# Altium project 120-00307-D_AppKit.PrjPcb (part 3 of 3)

## Sheet 13-JLINK_2.SchDoc: APP KIT BOARD
size 431 x 279 mm; Organization: ORGANIZATION; Address1: ADDRESS 1; Address2: ADDRESS 2; Address3: ADDRESS 3; Address4: ADDRESS 4; DocumentNumber: 13; Revision: -; SheetNumber: 13; SheetTotal: 14; ENG_APP_DATE: --/--/--; DSN_APP_DATE: --/--/--; CHK_APP_DATE: --/--/--
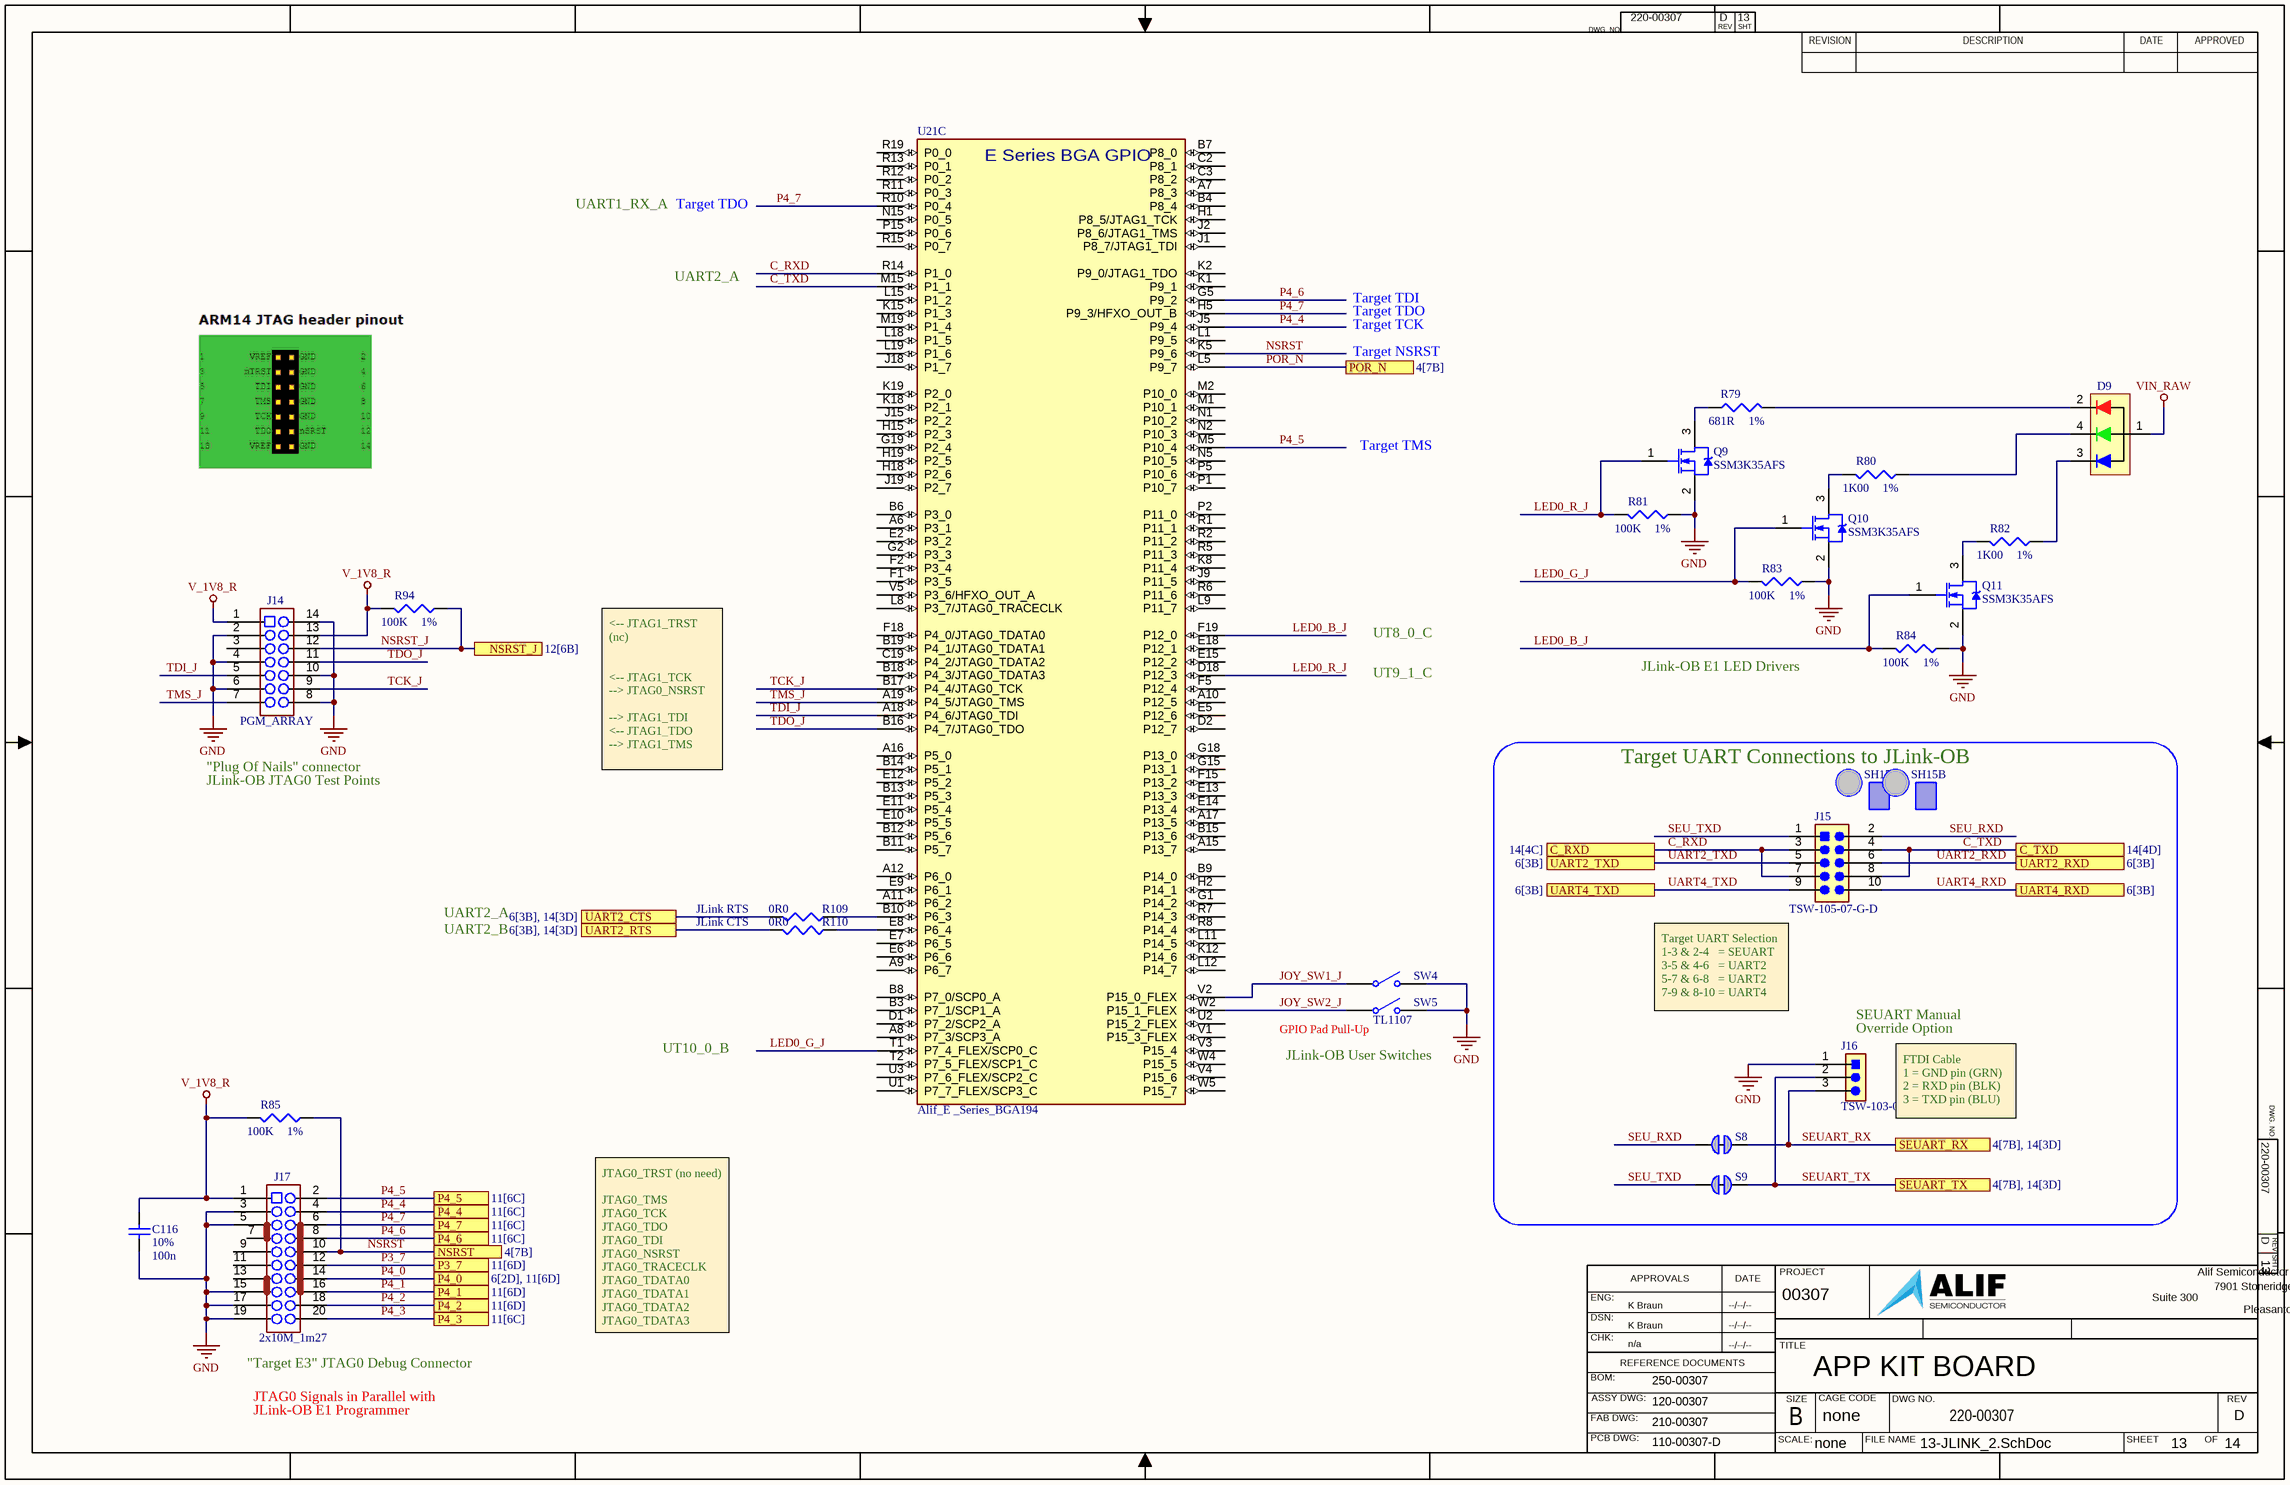
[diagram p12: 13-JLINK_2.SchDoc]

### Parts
C116  value 100n  Tolerance: 10%  [CAPC0402-01]  (hidden comment: Cap)
D9  SML-LX0404SIUPGUSB  [LED_SML-LX0404_LUM]  (value not drawn)
J14  value PGM_ARRAY  [TC2070-IDC]  (hidden comment: PGMG_CONTACT,14P,TC2070-IDC_1)  (no BOM)
J15  TSW-105-07-G-D  [CONN_TSW-105-07-G-D_SAI]
J16  TSW-103-07-G-S  [CONN_HDR_1X3_STRT_0.100]
J17  value 2x10M_1m27  [SAMTEC_FTSH-110-01-X-DV-007-K]  (hidden comment: Hdr_M_2X10_1M27_STRT_KEY_CORTEX_1)
Q9  Manufacturer Part Number 1: SSM3K35AFS  [SC75_SSM_TOS-L]  (hidden comment: NMOS-2_SOT)
Q10  Manufacturer Part Number 1: SSM3K35AFS  [SC75_SSM_TOS-L]  (hidden comment: NMOS-2_SOT)
Q11  Manufacturer Part Number 1: SSM3K35AFS  [SC75_SSM_TOS-L]  (hidden comment: NMOS-2_SOT)
R79  value 681R  Tolerance: 1%  [RESC0402-01]  (hidden comment: Res3)
R80  value 1K00  Tolerance: 1%  [RESC0402-01]  (hidden comment: Res3)
R81  value 100K  Tolerance: 1%  [RESC0402-01]  (hidden comment: Res3)
R82  value 1K00  Tolerance: 1%  [RESC0402-01]  (hidden comment: Res3)
R83  value 100K  Tolerance: 1%  [RESC0402-01]  (hidden comment: Res3)
R84  value 100K  Tolerance: 1%  [RESC0402-01]  (hidden comment: Res3)
R85  value 100K  Tolerance: 1%  [RESC0402-01]  (hidden comment: Res3)
R94  value 100K  Tolerance: 1%  [RESC0402-01]  (hidden comment: Res3)
R109  value 0R0  [RESC0402-01]  (hidden comment: Res3)
R110  value 0R0  [RESC0402-01]  (hidden comment: Res3)
S8  SolderJumperShorted_Small  [Solderbridge_Shorted]  (value not drawn)  (net tie, no BOM)
S9  SolderJumperShorted_Small  [Solderbridge_Shorted]  (value not drawn)  (net tie, no BOM)
SH15A  Shunt  (value not drawn)  (mechanical)
SH15B  Shunt  (value not drawn)  (mechanical)
SW4  SW-SPST  [SW_1825966-TL1107-1]  (value not drawn)
SW5  value TL1107  [SW_1825966-TL1107-1]  (hidden comment: SW-SPST)
U21  Alif_E _Series_BGA194  [BGA194 _CENTERED]  (part C of 4)

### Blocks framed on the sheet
Target UART Connections to JLink-OB: J15 J16 S8 S9 SH15A SH15B

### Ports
C_RXD (see 14[4C]), C_TXD (see 14[4D]), NSRST (see 4[7B]), NSRST_J (see 12[6B]), P3_7 (see 11[6D]), P4_0 (see 6[2D], 11[6D]), P4_1 (see 11[6D]), P4_2 (see 11[6D]), P4_3 (see 11[6C]), P4_4 (see 11[6C]), P4_5 (see 11[6C]), P4_6 (see 11[6C]), P4_7 (see 11[6C]), POR_N (see 4[7B]), SEUART_RX (see 4[7B], 14[3D]), SEUART_TX (see 4[7B], 14[3D]), UART2_CTS (see 6[3B], 14[3D]), UART2_RTS (see 6[3B], 14[3D]), UART2_RXD (see 6[3B]), UART2_TXD (see 6[3B]), UART4_RXD (see 6[3B]), UART4_TXD (see 6[3B])

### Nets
GND: C116.2 J14.2 J14.4 J14.6 J14.8 J14.10 J14.14 J16.1 J17.3 J17.5 J17.15 J17.17 J17.19 Q9.2(S) Q10.2(S) Q11.2(S) R81.1 R83.1 R84.1 SW4.2(NO) SW5.2(NO)
V_1V8_R: C116.1 J14.1 J14.13 J17.1 R85.2 R94.2
VIN_RAW: D9.1(A)
C_RXD: J15.3 J15.7 U21.R14(P1_0) ; port C_RXD
C_TXD: J15.4 J15.8 U21.M15(P1_1) ; port C_TXD
JOY_SW1_J: SW4.1(COMMON) U21.V2(P15_0_FLEX)
JOY_SW2_J: SW5.1(COMMON) U21.W2(P15_1_FLEX)
LED0_B_J: Q11.1(G) R84.2 U21.F19(P12_0)
LED0_G_J: Q10.1(G) R83.2 U21.T1(P7_4_FLEX/SCP0_C)
LED0_R_J: Q9.1(G) R81.2 U21.D18(P12_3)
NSRST: J17.10 R85.1 U21.K5(P9_6) ; port NSRST
NSRST_J: J14.12 R94.1 ; port NSRST_J
P3_7: J17.12 ; port P3_7
P4_0: J17.14 ; port P4_0
P4_1: J17.16 ; port P4_1
P4_2: J17.18 ; port P4_2
P4_3: J17.20 ; port P4_3
P4_4: J17.4 U21.J5(P9_4) ; port P4_4
P4_5: J17.2 U21.M5(P10_4) ; port P4_5
P4_6: J17.8 U21.G5(P9_2) ; port P4_6
P4_7: J17.6 U21.H5(P9_3/HFXO_OUT_B) U21.R10(P0_4) ; port P4_7
P6_3: R109.2 ; port UART2_CTS
P6_4: R110.2 ; port UART2_RTS
POR_N: U21.L5(P9_7) ; port POR_N
SEU_RXD: J15.2 S8.1
SEU_TXD: J15.1 S9.1
SEUART_RX: J16.3 S8.2 ; port SEUART_RX
SEUART_TX: J16.2 S9.2 ; port SEUART_TX
TCK_J: J14.9 U21.B17(P4_4/JTAG0_TCK)
TDI_J: J14.5 U21.A18(P4_6/JTAG0_TDI)
TDO_J: J14.11 U21.B16(P4_7/JTAG0_TDO)
TMS_J: J14.7 U21.A19(P4_5/JTAG0_TMS)
UART2_RXD: J15.6 ; port UART2_RXD  [project net P1_0]
UART2_TXD: J15.5 ; port UART2_TXD  [project net P1_1]
UART4_RXD: J15.10 ; port UART4_RXD  [project net P12_1]
UART4_TXD: J15.9 ; port UART4_TXD  [project net P12_2]
NetD9_2: D9.2(RK) R79.2
NetD9_3: D9.3(BK) R82.1
NetD9_4: D9.4(GK) R80.1
NetQ9_3: Q9.3(D) R79.1
NetQ10_3: Q10.3(D) R80.2
NetQ11_3: Q11.3(D) R82.2
NetR109_1: R109.1 U21.B10(P6_3)
NetR110_1: R110.1 U21.E8(P6_4)

Not connected (* = marked no-connect by the designer): J14 3; J17 7 9 11 13; U21 A6(P3_1) A7(P8_3) A8(P7_3/SCP3_A) A9(P6_7) A10(P12_5) A11(P6_2) A12(P6_0) A15(P13_7) A16(P5_0) A17(P13_5) B3(P7_1/SCP1_A) B4(P8_4) B6(P3_0) B7(P8_0) B8(P7_0/SCP0_A) B9(P14_0) B11(P5_7) B12(P5_6) B13(P5_3) B14(P5_1) B15(P13_6) B18(P4_3/JTAG0_TDATA3) B19(P4_1/JTAG0_TDATA1) C2(P8_1) C3(P8_2) C19(P4_2/JTAG0_TDATA2) D1(P7_2/SCP2_A) D2(P12_7) E2(P3_2) E5(P12_6) E6(P6_6) E7(P6_5) E9(P6_1) E10(P5_5) E11(P5_4) E12(P5_2) E13(P13_3) E14(P13_4) E15(P12_2) E18(P12_1) F1(P3_5) F2(P3_4) F5(P12_4) F15(P13_2) F18(P4_0/JTAG0_TDATA0) G1(P14_2) G2(P3_3) G15(P13_1) G18(P13_0) G19(P2_4) H1(P8_5/JTAG1_TCK) H2(P14_1) H15(P2_3) H18(P2_6) H19(P2_5) J1(P8_7/JTAG1_TDI) J2(P8_6/JTAG1_TMS) J9(P11_5) J15(P2_2) J18(P1_7) J19(P2_7) K1(P9_1) K2(P9_0/JTAG1_TDO) K8(P11_4) K12(P14_6) K15(P1_3) K18(P2_1) K19(P2_0) L1(P9_5) L8(P3_7/JTAG0_TRACECLK) L9(P11_7) L11(P14_5) L12(P14_7) L15(P1_2) L18(P1_5) L19(P1_6) M1(P10_1) M2(P10_0) M19(P1_4) N1(P10_2) N2(P10_3) N5(P10_5) N15(P0_5) P1(P10_7) P2(P11_0) P5(P10_6) P15(P0_6) R1(P11_1) R2(P11_2) R5(P11_3) R6(P11_6) R7(P14_3) R8(P14_4) R11(P0_3) R12(P0_2) R13(P0_1) R15(P0_7) R19(P0_0) T2(P7_5_FLEX/SCP1_C) U1(P7_7_FLEX/SCP3_C) U2(P15_2_FLEX) U3(P7_6_FLEX/SCP2_C) V1(P15_3_FLEX) V3(P15_4) V4(P15_6) V5(P3_6/HFXO_OUT_A) W4(P15_5) W5(P15_7)

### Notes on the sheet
- UART1_RX_A
- Target TDO
- UART2_A
- Target TDI
- Target TCK
- Target NSRST
- Target TMS
- UT8_0_C
- UT9_1_C
- JLink-OB E1 LED Drivers
- <-- JTAG1_TRST (nc)
  <-- JTAG1_TCK
  --> JTAG0_NSRST
  --> JTAG1_TDI
  <-- JTAG1_TDO
  --> JTAG1_TMS
- JLink-OB JTAG0 Test Points
- "Plug Of Nails" connector
- UART2_B
- JLink RTS
- JLink CTS
- (near SW5) GPIO Pad Pull-Up
- (near J15) Target UART Selection
  1-3 & 2-4   = SEUART
  3-5 & 4-6   = UART2
  5-7 & 6-8   = UART2
  7-9 & 8-10 = UART4
- (near J16) SEUART Manual
- (near J16) Override Option
- UT10_0_B
- (near SW5) JLink-OB User Switches
- FTDI Cable
  1 = GND pin (GRN)
  2 = RXD pin (BLK)
  3 = TXD pin (BLU)
- (near J17) "Target E3" JTAG0 Debug Connector
- JTAG0_TRST (no need)
  JTAG0_TMS
  JTAG0_TCK
  JTAG0_TDO
  JTAG0_TDI
  JTAG0_NSRST
  JTAG0_TRACECLK
  JTAG0_TDATA0
  JTAG0_TDATA1
  JTAG0_TDATA2
  JTAG0_TDATA3
- JTAG0 Signals in Parallel with
- JLink-OB E1 Programmer

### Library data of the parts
C116 = Cap: Cap,100nF,10%,50V,X7R,0402; Manufacturer 1: TDK; Manufacturer Part Number 1: C1005X7R1H104K050BE; PCB_Footprint: CC0402
D9 = D LED_RGB_CA_1MMc1MM: Diode,LED,RGB, (@2mA) -> R=10mcd & 1.75V, G = 50mcd & 2.75V, B = 20mcd & 2.95V, 0404(1mm x 1mm); Manufacturer 1: Lumex
J14 = PGMG_CONTACT,14P,TC2070-IDC_1: Test Point, Array, Alignment Pins, SMT Pad,--not a BOM item--
J15 = Hdr_M_2X5_2M54_STRT_UNSHROUDED: Hdr, Male,2x5, 2.54mm, 0.230mate,0.100-0.120post,Strt; Manufacturer 1: Samtec; Manufacturer Part Number 1: TSW-105-07-L-D
J16 = Hdr_M_1X3_2M54_STRT_UNSHROUD: Hdr, 0.025" SQ Post Header, Through-hole, Vertical, -55 to 125 degC, 2.54 mm Pitch, 3-Pin, Male, RoHS; Manufacturer: Samtec; Manufacturer Part Number 1: TSW-103-07-L-S; Pitch: 2.54 mm
J17 = Hdr_M_2X10_1M27_STRT_KEY_CORTEX_1: Hdr,Male,2x10,1.27mm,Strt,Keyed,Cortex-JTAG; Manufacturer 1: Samtec; Manufacturer Part Number 1: FTSH-110-01-L-DV-007-K; PCB_Footprint: FTSH-110-01-X-DV-007-K
Q9-Q11 = NMOS-2_SOT: MOSFET,N-CH,20V,250mA,1.1Ohm,SOT-23; Manufacturer 1: Toshiba; Note: Pin 2 is electrically connected to pin 4.; Value: 20V  180mA  2.4Ohm
R79 = Res3: Res,681R,1%,100ppm,0402; Manufacturer 1: Stackpol; Manufacturer Part Number 1: RMCF0402FT681R; Wattage: 63mW
R80 R82 = Res3: Res,1K00,1%,100ppm,0402; Manufacturer 1: Stackpol; Manufacturer Part Number 1: RMCF0402FT1K; Wattage: 63mW
R81 R83-R85 R94 = Res3: Res,100K,1%,100ppm,0402; Manufacturer 1: Stackpol; Manufacturer Part Number 1: RMCF0402FT100K; Wattage: 63mW
R109 R110 = Res3: Res,0R ohm,Jumper,0402; Manufacturer 1: Stackpol; Manufacturer Part Number 1: RMCF0402ZT0R00; Wattage: 63mW; Tolerance: JMPR
S8 S9 = SolderJumperShorted_Small: DNI,Solderable Jumper,Shorted; Wattage: 63mW; PCB_Footprint: SSHORTED
SH15A SH15B = SHUNT_F_1x2_2.5MM_STRT: Shunt,Female,1x2,2.54mm,Gold,Strt; Manufacturer 1: Samtec; Manufacturer Part Number 1: SNT-100-BK-H
SW4 = SW-SPST: Swit, SPST, Momentary Pushputton, 2 pin, 6.0x3.5mm, H=5.0mm; Manufacturer 1: E-Switch; Manufacturer Part Number 1: TL1107BF180WQ; Value: TL1107
SW5 = SW-SPST: Swit, SPST, Momentary Pushputton, 2 pin, 6.0x3.5mm, H=5.0mm; Manufacturer 1: E-Switch; Manufacturer Part Number 1: TL1107BF180WQ
U21 = E7_B0_194BGA: IC,Alif E7 MCU, Rev B silicon,BGA194; Manufacturer 1: Alif Semi; Manufacturer Part Number 1: AE101F4071542LH

## Sheet 14-CypressSEUART.SchDoc: APP KIT BOARD
size 431 x 279 mm; Organization: ORGANIZATION; Address1: ADDRESS 1; Address2: ADDRESS 2; Address3: ADDRESS 3; Address4: ADDRESS 4; DocumentNumber: 14; Revision: -; SheetNumber: 14; SheetTotal: 14; ENG_APP_DATE: --/--/--; DSN_APP_DATE: --/--/--; CHK_APP_DATE: --/--/--
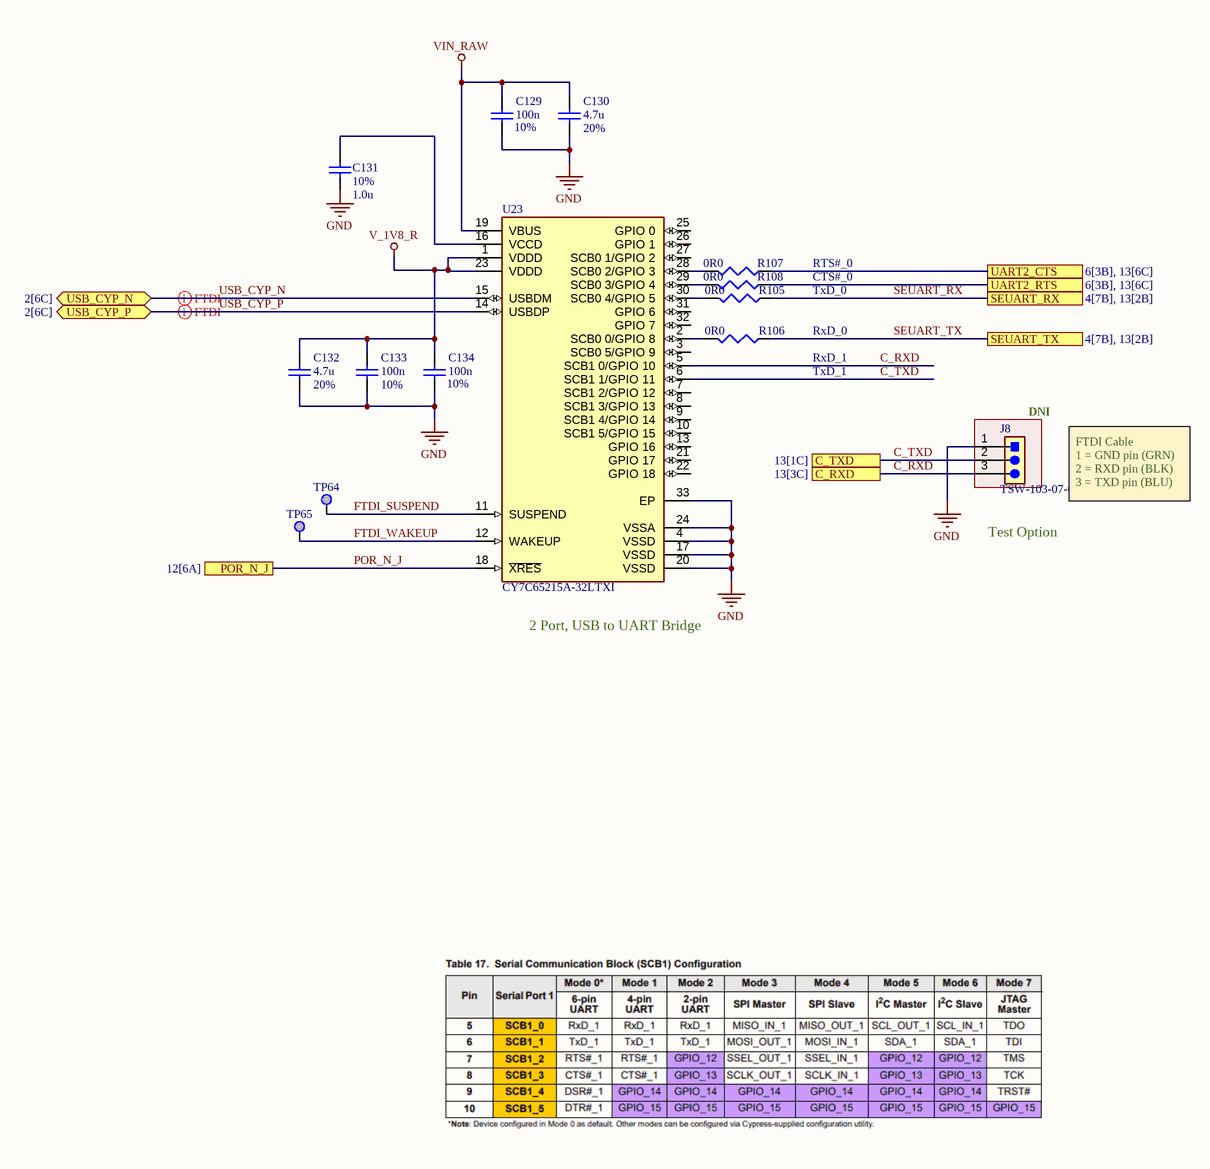
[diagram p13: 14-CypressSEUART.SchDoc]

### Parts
C129  value 100n  Tolerance: 10%  [CAPC0402-01]  (hidden comment: Cap)
C130  value 4.7u  Tolerance: 20%  [CAPC0402-01]  (hidden comment: Cap)
C131  value 1.0u  Tolerance: 10%  [CAPC0402-01]  (hidden comment: Cap)
C132  value 4.7u  Tolerance: 20%  [CAPC0402-01]  (hidden comment: Cap)
C133  value 100n  Tolerance: 10%  [CAPC0402-01]  (hidden comment: Cap)
C134  value 100n  Tolerance: 10%  [CAPC0402-01]  (hidden comment: Cap)
J8  TSW-103-07-G-S  [CONN_HDR_1X3_STRT_0.100_no3D]
R105  value 0R0  [RESC0402-01]  (hidden comment: Res3)
R106  value 0R0  [RESC0402-01]  (hidden comment: Res3)
R107  value 0R0  [RESC0402-01]  (hidden comment: Res3)
R108  value 0R0  [RESC0402-01]  (hidden comment: Res3)
TP64  TP_SMPAD  [TP_50_RND]  (value not drawn)  (no BOM)
TP65  TP_SMPAD  [TP_50_RND]  (value not drawn)  (no BOM)
U23  CY7C65215A-32LTXI  [QFN32_5x5x1-0p5_INF-M]

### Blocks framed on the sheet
DNI: J8

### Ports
C_RXD (see 13[3C]), C_TXD (see 13[1C]), POR_N_J (see 12[6A]), SEUART_RX (see 4[7B], 13[2B]), SEUART_TX (see 4[7B], 13[2B]), UART2_CTS (see 6[3B], 13[6C]), UART2_RTS (see 6[3B], 13[6C]), USB_CYP_N (bidir, see 2[6C]), USB_CYP_P (bidir, see 2[6C])

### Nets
GND: C129.1 C130.1 C131.1 C132.1 C133.1 C134.1 J8.1 U23.4(VSSD) U23.17(VSSD) U23.20(VSSD) U23.24(VSSA) U23.33(EP)
V_1V8_R: C132.2 C133.2 C134.2 U23.1(VDDD) U23.23(VDDD)
VIN_RAW: C129.2 C130.2 U23.19(VBUS)
C_RXD: J8.3 U23.5(SCB1_0/GPIO_10) ; port C_RXD
C_TXD: J8.2 U23.6(SCB1_1/GPIO_11) ; port C_TXD
FTDI_SUSPEND: TP64.1 U23.11(SUSPEND)
FTDI_WAKEUP: TP65.1 U23.12(WAKEUP)
P6_3: R107.1 ; port UART2_CTS
P6_4: R108.1 ; port UART2_RTS
POR_N_J: U23.18(~{XRES}) ; port POR_N_J
SEUART_RX: R105.1 ; port SEUART_RX
SEUART_TX: R106.1 ; port SEUART_TX
USB_CYP_N: U23.15(USBDM) ; port USB_CYP_N
USB_CYP_P: U23.14(USBDP) ; port USB_CYP_P
NetC131_2: C131.2 U23.16(VCCD)
NetR105_2: R105.2 U23.30(SCB0_4/GPIO_5)
NetR106_2: R106.2 U23.2(SCB0_0/GPIO_8)
NetR107_2: R107.2 U23.28(SCB0_2/GPIO_3)
NetR108_2: R108.2 U23.29(SCB0_3/GPIO_4)

Not connected (* = marked no-connect by the designer): U23 3(SCB0_5/GPIO_9) 7(SCB1_2/GPIO_12) 8(SCB1_3/GPIO_13) 9(SCB1_4/GPIO_14) 10(SCB1_5/GPIO_15) 13(GPIO_16) 21(GPIO_17) 22(GPIO_18) 25(GPIO_0) 26(GPIO_1) 27(SCB0_1/GPIO_2) 31(GPIO_6) 32(GPIO_7)

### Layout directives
differential pair; differential pair class USB_CYP_: USB_CYP_N, USB_CYP_P

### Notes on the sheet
- RTS#_0
- CTS#_0
- RxD_0
- TxD_0
- RxD_1
- TxD_1
- (near J8) Test Option
- FTDI Cable
  1 = GND pin (GRN)
  2 = RXD pin (BLK)
  3 = TXD pin (BLU)
- (near U23) 2 Port, USB to UART Bridge

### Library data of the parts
C129 C133 C134 = Cap: as C116 on sheet 13-JLINK_2
C130 C132 = Cap_225M25VX5R0402_1: Cap,4.7uF,20%,10V,X5R,0402; Manufacturer 1: TDK; Manufacturer Part Number 1: C1005X5R1A475K050BC; PCB_Footprint: CC0402
C131 = Cap: Cap,1.0uF,20%,25V,X5R,0402; Manufacturer 1: TDK; Manufacturer Part Number 1: CGB2A1X5R1E105K033BC; PCB_Footprint: CC0402
J8 = Hdr_M_1X3_2M54_STRT_UNSHROUD: DNI,Hdr, 0.025" SQ Post Header, Through-hole, Vertical, -55 to 125 degC, 2.54 mm Pitch, 3-Pin, Male, RoHS; Manufacturer: Samtec; Pitch: 2.54 mm
R105-R108 = Res3: as R109 on sheet 13-JLINK_2
TP64 TP65 = TP_SMPAD: DNI,Test Point, SMT Pad,--not a BOM item--; PCB_Footprint: TP_PAD1
U23 = IC_Dual_USB_UART_Bridge: IC,Dual USB to Serial Bridge,32QFN; Manufacturer 1: Cypress; Import Ts: 1521861523; Ciiva Ids: 12522558; Interface: I2C,SPI,UART,USB; Min Supply Voltage: 1.71V; Standoff Height: 0mm; Max Supply Voltage: 5.5V; Nominal Supply Current: 13mA

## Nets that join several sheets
GND: 2-PowerInput (44 pins), 3-CPUPower (39 pins), 4-CPUMipiXoMemory (19 pins), 5-WiFi (60 pins), 7-CODEC (13 pins), 8-Sensors (24 pins), 9-MIPI_CSI (49 pins), 10-MIPI_DSI (23 pins), 12-JLINK_1 (42 pins), 13-JLINK_2 (21 pins), 14-CypressSEUART (12 pins)
USB_D_VBUS: 2-PowerInput (5 pins), 4-CPUMipiXoMemory (R100.1)
USB_U_VBUS: 2-PowerInput (5 pins), 12-JLINK_1 (R103.1)
V_1V8_R: 2-PowerInput (S2.2 TP2.1), 3-CPUPower (J4.2), 4-CPUMipiXoMemory (19 pins), 5-WiFi (12 pins), 6-GPIOTranslate (R48.1 R49.1 R52.1 R53.1), 7-CODEC (9 pins), 8-Sensors (15 pins), 9-MIPI_CSI (6 pins), 10-MIPI_DSI (5 pins), 12-JLINK_1 (9 pins), 13-JLINK_2 (6 pins), 14-CypressSEUART (5 pins)
V_3V3: 2-PowerInput (R5.1 S1.2 TP1.1), 3-CPUPower (J3.2), 5-WiFi (C54.2 Q7.4 R42.1 R43.2), 10-MIPI_DSI (5 pins), 12-JLINK_1 (8 pins)
VDD_IOFLEX: 3-CPUPower (C28.2 J5.2 U3.W1), 6-GPIOTranslate (R50.1 R51.1), 8-Sensors (7 pins)
VIN_RAW: 2-PowerInput (11 pins), 7-CODEC (C73.2 R60.2 U12.1), 9-MIPI_CSI (C93.2 C95.2 U19.1 U20.1), 10-MIPI_DSI (C122.2 C123.1 L5.1 U22.5), 13-JLINK_2 (D9.1), 14-CypressSEUART (C129.2 C130.2 U23.19)
C_EN_MIPI_PWR: 9-MIPI_CSI (R72.2 U19.3 U20.3), 11-CPU_GPIO (U3.T2)
C_RESETn: 9-MIPI_CSI (J10.21 J12.21 R69.2), 11-CPU_GPIO (U3.K1)
C_RXD: 13-JLINK_2 (J15.3 J15.7 U21.R14), 14-CypressSEUART (J8.3 U23.5)
C_TXD: 13-JLINK_2 (J15.4 J15.8 U21.M15), 14-CypressSEUART (J8.2 U23.6)
D_RESETn: 10-MIPI_DSI (J18.9 R86.2), 11-CPU_GPIO (U3.W4)
I2C_CL_SCL: 6-GPIOTranslate (R52.2), 7-CODEC (U11.2), 11-CPU_GPIO (U3.F2)
I2C_CL_SDA: 6-GPIOTranslate (R53.2), 7-CODEC (U11.3), 11-CPU_GPIO (U3.F1)
I2C_FB_SCL: 5-WiFi (U10.3), 6-GPIOTranslate (R48.2), 9-MIPI_CSI (J10.14 J12.14), 10-MIPI_DSI (J20.4), 11-CPU_GPIO (U3.A8)
I2C_FB_SDA: 5-WiFi (U10.2), 6-GPIOTranslate (R49.2), 9-MIPI_CSI (J10.22 J12.22), 10-MIPI_DSI (J20.5), 11-CPU_GPIO (U3.D1)
I3C_SCL: 6-GPIOTranslate (R50.2), 8-Sensors (U14.13 U16.13), 11-CPU_GPIO (U3.U1)
I3C_SDA: 6-GPIOTranslate (R51.2), 8-Sensors (U14.14 U16.14), 11-CPU_GPIO (U3.U3)
LFXO_N: 4-CPUMipiXoMemory (U3.V17 Y2.1), 12-JLINK_1 (R111.2)
MIPI_CSI_0_N: 4-CPUMipiXoMemory (U3.V14), 9-MIPI_CSI (J10.5 J12.5 TP43.1)
MIPI_CSI_0_P: 4-CPUMipiXoMemory (U3.W14), 9-MIPI_CSI (J10.4 J12.4 TP42.1)
MIPI_CSI_1_N: 4-CPUMipiXoMemory (U3.V15), 9-MIPI_CSI (J10.29 J12.29 TP41.1)
MIPI_CSI_1_P: 4-CPUMipiXoMemory (U3.W15), 9-MIPI_CSI (J10.30 J12.30 TP40.1)
MIPI_CSI_C_N: 4-CPUMipiXoMemory (U3.V16), 9-MIPI_CSI (J10.8 J12.8 TP38.1)
MIPI_CSI_C_P: 4-CPUMipiXoMemory (U3.W16), 9-MIPI_CSI (J10.7 J12.7 TP37.1)
MIPI_DSI_0_N: 4-CPUMipiXoMemory (U3.V11), 10-MIPI_DSI (J18.18 TP58.1)
MIPI_DSI_0_P: 4-CPUMipiXoMemory (U3.W11), 10-MIPI_DSI (J18.17 TP59.1)
MIPI_DSI_1_N: 4-CPUMipiXoMemory (U3.V9), 10-MIPI_DSI (J18.12 TP62.1)
MIPI_DSI_1_P: 4-CPUMipiXoMemory (U3.W9), 10-MIPI_DSI (J18.11 TP63.1)
MIPI_DSI_C_N: 4-CPUMipiXoMemory (U3.V10), 10-MIPI_DSI (J18.15 TP60.1)
MIPI_DSI_C_P: 4-CPUMipiXoMemory (U3.W10), 10-MIPI_DSI (J18.14 TP61.1)
NSRST: 4-CPUMipiXoMemory (U3.J12), 13-JLINK_2 (J17.10 R85.1 U21.K5)
NSRST_J: 12-JLINK_1 (U21.J12), 13-JLINK_2 (J14.12 R94.1)
OSPI0_D0: 4-CPUMipiXoMemory (U5.D3), 11-CPU_GPIO (U3.K19)
OSPI0_D1: 4-CPUMipiXoMemory (U5.D2), 11-CPU_GPIO (U3.K18)
OSPI0_D2: 4-CPUMipiXoMemory (U5.C4), 11-CPU_GPIO (U3.J15)
OSPI0_D3: 4-CPUMipiXoMemory (U5.D4), 11-CPU_GPIO (U3.H15)
OSPI0_D4: 4-CPUMipiXoMemory (U5.D5), 11-CPU_GPIO (U3.G19)
OSPI0_D5: 4-CPUMipiXoMemory (U5.E3), 11-CPU_GPIO (U3.H19)
OSPI0_D6: 4-CPUMipiXoMemory (U5.E2), 11-CPU_GPIO (U3.H18)
OSPI0_D7: 4-CPUMipiXoMemory (U5.E1), 11-CPU_GPIO (U3.J19)
OSPI0_RESETn: 4-CPUMipiXoMemory (U5.A4), 11-CPU_GPIO (U3.V4)
OSPI0_RXDS: 4-CPUMipiXoMemory (R35.1), 11-CPU_GPIO (U3.L19)
OSPI0_SCLK: 4-CPUMipiXoMemory (U5.B2), 11-CPU_GPIO (U3.B6)
OSPI0_SCLKN: 4-CPUMipiXoMemory (U5.B1), 11-CPU_GPIO (U3.A6)
OSPI0_SS0: 4-CPUMipiXoMemory (R31.2 R33.2 U5.C2), 6-GPIOTranslate (S6.1)
OSPI1_D0: 4-CPUMipiXoMemory (U4.D3), 11-CPU_GPIO (U3.L1)
OSPI1_D1: 4-CPUMipiXoMemory (U4.D2), 11-CPU_GPIO (U3.K5)
OSPI1_D2: 4-CPUMipiXoMemory (U4.C4), 11-CPU_GPIO (U3.L5)
OSPI1_D3: 4-CPUMipiXoMemory (U4.D4), 11-CPU_GPIO (U3.M2)
OSPI1_D4: 4-CPUMipiXoMemory (U4.D5), 11-CPU_GPIO (U3.M1)
OSPI1_D5: 4-CPUMipiXoMemory (U4.E3), 11-CPU_GPIO (U3.N1)
OSPI1_D6: 4-CPUMipiXoMemory (U4.E2), 11-CPU_GPIO (U3.N2)
OSPI1_D7: 4-CPUMipiXoMemory (U4.E1), 11-CPU_GPIO (U3.M5)
OSPI1_RESETn: 4-CPUMipiXoMemory (U4.A4), 11-CPU_GPIO (U3.W5)
OSPI1_RXDS: 4-CPUMipiXoMemory (R34.1), 11-CPU_GPIO (U3.P1)
OSPI1_SCLK: 4-CPUMipiXoMemory (U4.B2), 11-CPU_GPIO (U3.E10)
OSPI1_SCLKN: 4-CPUMipiXoMemory (U4.B1), 11-CPU_GPIO (U3.B7)
OSPI1_SS0: 4-CPUMipiXoMemory (R26.2 R32.2 U4.C2), 6-GPIOTranslate (S5.1)
P0_3: 9-MIPI_CSI (J10.32 J12.32), 11-CPU_GPIO (U3.R11)
P0_4: 5-WiFi (U6.3), 11-CPU_GPIO (U3.R10)
P0_5: 5-WiFi (U6.2), 11-CPU_GPIO (U3.N15)
P0_6: 5-WiFi (U6.5), 11-CPU_GPIO (U3.P15)
P0_7: 5-WiFi (U6.4), 11-CPU_GPIO (U3.R15)
P1_0: 11-CPU_GPIO (U3.R14), 13-JLINK_2 (J15.6)
P1_1: 11-CPU_GPIO (U3.M15), 13-JLINK_2 (J15.5)
P3_2: 6-GPIOTranslate (S6.2), 11-CPU_GPIO (U3.E2)
P3_7: 11-CPU_GPIO (U3.L8), 13-JLINK_2 (J17.12)
P4_0: 10-MIPI_DSI (J20.7 R90.2), 11-CPU_GPIO (U3.F18), 13-JLINK_2 (J17.14)
P4_1: 11-CPU_GPIO (U3.B19), 13-JLINK_2 (J17.16)
P4_2: 11-CPU_GPIO (U3.C19), 13-JLINK_2 (J17.18)
P4_3: 11-CPU_GPIO (U3.B18), 13-JLINK_2 (J17.20)
P4_4: 11-CPU_GPIO (U3.B17), 13-JLINK_2 (J17.4 U21.J5)
P4_5: 11-CPU_GPIO (U3.A19), 13-JLINK_2 (J17.2 U21.M5)
P4_6: 11-CPU_GPIO (U3.A18), 13-JLINK_2 (J17.8 U21.G5)
P4_7: 11-CPU_GPIO (U3.B16), 13-JLINK_2 (J17.6 U21.H5 U21.R10)
P5_4: 8-Sensors (R67.2 R68.2), 11-CPU_GPIO (U3.E11)
P5_7: 6-GPIOTranslate (S5.2), 11-CPU_GPIO (U3.B11)
P6_1: 10-MIPI_DSI (R88.2 U22.4), 11-CPU_GPIO (U3.E9)
P6_2: 2-PowerInput (Q4.1 R22.2), 11-CPU_GPIO (U3.A11)
P6_3: 11-CPU_GPIO (U3.B10), 13-JLINK_2 (R109.2), 14-CypressSEUART (R107.1)
P6_4: 11-CPU_GPIO (U3.E8), 13-JLINK_2 (R110.2), 14-CypressSEUART (R108.1)
P6_5: 2-PowerInput (Q5.1 R24.2), 11-CPU_GPIO (U3.E7)
P6_6: 2-PowerInput (Q6.1 R25.2), 11-CPU_GPIO (U3.E6)
P6_7: 8-Sensors (U17.6 U18.6), 11-CPU_GPIO (U3.A9)
P7_4: 2-PowerInput (Q2.1 R18.2), 11-CPU_GPIO (U3.T1)
P8_1: 7-CODEC (U11.31), 11-CPU_GPIO (U3.C2)
P8_2: 7-CODEC (U11.32), 11-CPU_GPIO (U3.C3)
P8_3: 7-CODEC (U11.29), 11-CPU_GPIO (U3.A7)
P8_4: 8-Sensors (U16.4), 11-CPU_GPIO (U3.B4)
P8_5: 8-Sensors (U14.4), 11-CPU_GPIO (U3.H1)
P8_6: 8-Sensors (U13.6 U15.6), 11-CPU_GPIO (U3.J2)
P8_7: 8-Sensors (U13.1 U15.1), 11-CPU_GPIO (U3.J1)
P9_0: 8-Sensors (R64.2 R65.2), 11-CPU_GPIO (U3.K2)
P9_2: 9-MIPI_CSI (J10.15 J12.15), 11-CPU_GPIO (U3.G5)
P9_3: 9-MIPI_CSI (J10.20 J12.20), 11-CPU_GPIO (U3.H5)
P9_4: 10-MIPI_DSI (R91.1 R92.1), 11-CPU_GPIO (U3.J5)
P11_0: 7-CODEC (U11.30), 11-CPU_GPIO (U3.P2)
P12_0: 2-PowerInput (Q3.1 R19.2), 11-CPU_GPIO (U3.F19)
P12_1: 11-CPU_GPIO (U3.E18), 13-JLINK_2 (J15.10)
P12_2: 11-CPU_GPIO (U3.E15), 13-JLINK_2 (J15.9)
P12_3: 2-PowerInput (Q1.1 R15.2), 11-CPU_GPIO (U3.D18)
P12_4: 5-WiFi (U8.3), 11-CPU_GPIO (U3.F5)
P12_5: 5-WiFi (U8.4), 11-CPU_GPIO (U3.A10)
P12_6: 5-WiFi (U8.5), 11-CPU_GPIO (U3.E5)
P12_7: 5-WiFi (U8.2), 11-CPU_GPIO (U3.D2)
P13_0: 5-WiFi (R93.2), 11-CPU_GPIO (U3.G18)
P13_1: 5-WiFi (U9.2), 11-CPU_GPIO (U3.G15)
P13_2: 5-WiFi (R45.1 U9.5), 11-CPU_GPIO (U3.F15)
P13_3: 5-WiFi (U9.4), 11-CPU_GPIO (U3.E13)
P14_2: 7-CODEC (U11.1), 11-CPU_GPIO (U3.G1)
P15_0: 8-Sensors (SW2.1), 11-CPU_GPIO (U3.V2)
P15_1: 8-Sensors (SW2.4), 11-CPU_GPIO (U3.W2)
P15_2: 8-Sensors (SW2.3), 11-CPU_GPIO (U3.U2)
P15_3: 8-Sensors (SW2.6), 11-CPU_GPIO (U3.V1)
P15_4: 8-Sensors (SW2.2), 11-CPU_GPIO (U3.V3)
POR_N: 4-CPUMipiXoMemory (R39.1 SW1.1 U3.U18), 13-JLINK_2 (U21.L5)
POR_N_J: 12-JLINK_1 (R78.1 SW3.3 U21.U18), 14-CypressSEUART (U23.18)
SEUART_RX: 4-CPUMipiXoMemory (U3.A14), 13-JLINK_2 (J16.3 S8.2), 14-CypressSEUART (R105.1)
SEUART_TX: 4-CPUMipiXoMemory (U3.A13), 13-JLINK_2 (J16.2 S9.2), 14-CypressSEUART (R106.1)
USB_CYP_N: 2-PowerInput (R97.1), 14-CypressSEUART (U23.15)
USB_CYP_P: 2-PowerInput (R98.1), 14-CypressSEUART (U23.14)
USB_DEV_N: 2-PowerInput (D1.6), 4-CPUMipiXoMemory (U3.V7)
USB_DEV_P: 2-PowerInput (D1.4), 4-CPUMipiXoMemory (U3.W7)
USB_FTDI_N: 2-PowerInput (R95.1), 12-JLINK_1 (U21.V7)
USB_FTDI_P: 2-PowerInput (R96.1), 12-JLINK_1 (U21.W7)
USB_ID: 2-PowerInput (R8.2 R12.1), 4-CPUMipiXoMemory (U3.R9)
